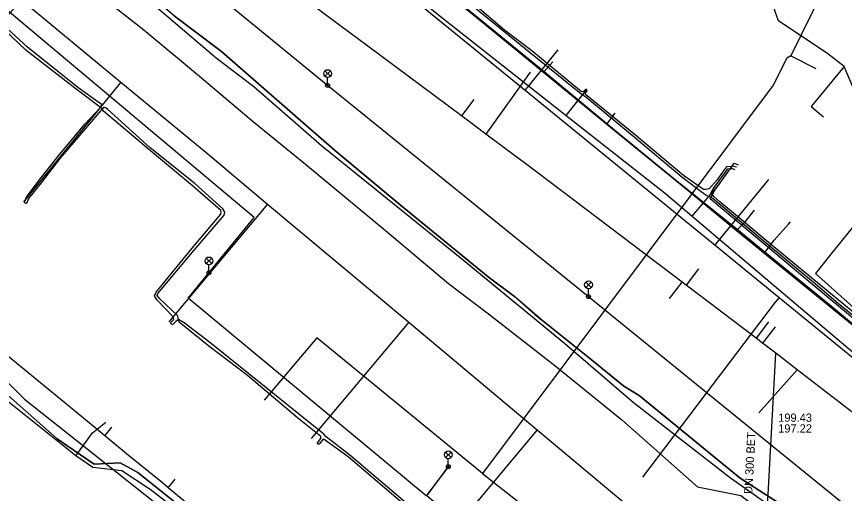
# Model space of a CAD drawing. Extents: x -598932 to -598196, y -1162210 to -1161504.
# Drawn here: x -598553.2 to -598473, y -1161902.1 to -1161855.8 of the extents above; entities that cross this region are included whole.
import ezdxf

# ---------------------------------------------------------------- set-up
doc = ezdxf.new("R2010")
doc.units = 0
for name, color, linetype in [('Vrstva 1', 7, 'Continuous'), ('Vrstva 12', 7, 'Continuous'), ('Vrstva 13', 7, 'Continuous'), ('Vrstva 14', 7, 'Continuous'), ('Vrstva 16', 7, 'Continuous'), ('Vrstva 33', 7, 'Continuous'), ('Vrstva 37', 7, 'Continuous'), ('Vrstva 42', 7, 'Continuous'), ('Vrstva 53', 7, 'Continuous'), ('Vrstva 55', 7, 'Continuous'), ('Vrstva 58', 7, 'Continuous'), ('Vrstva 9', 7, 'Continuous')]:
    doc.layers.add(name, color=color, linetype=linetype)

msp = doc.modelspace()

# ---------------------------------------------------------------- linework, layer by layer
at = {"layer": 'Vrstva 1'}
for p, q in [((-598503.44, -1161861.23), (-598507.733, -1161867.234)), ((-598481.27, -1161894.25), (-598477.545, -1161890.076))]:
    msp.add_line(p, q, dxfattribs=at)
at = {"layer": 'Vrstva 12'}
for p, q in [((-598502.08, -1161861.17), (-598501.22, -1161860.24)), ((-598545.86, -1161896.2), (-598544.55, -1161895.17)), ((-598547.47, -1161898.43), (-598545.86, -1161896.2)), ((-598538.51, -1161901.53), (-598538.57, -1161901.48))]:
    msp.add_line(p, q, dxfattribs=at)
for points in [[(-598614.66, -1161837.53), (-598611.92, -1161843.76), (-598592.64, -1161859.53), (-598589.54, -1161862.06), (-598564.16, -1161882.82), (-598561.07, -1161885.35), (-598555.73, -1161889.71), (-598552.43, -1161892.94), (-598535.8, -1161906.11), (-598532.7, -1161908.64), (-598530.18, -1161910.6)], [(-598515.13, -1161850.5), (-598508.89, -1161855.62), (-598502.08, -1161861.17)], [(-598502.08, -1161861.17), (-598494.86, -1161867.14), (-598489.18, -1161871.8), (-598483.57, -1161876.3), (-598480.65, -1161878.7)], [(-598480.65, -1161878.7), (-598479.77, -1161877.53), (-598478.39, -1161875.98), (-598478.18, -1161875.75)], [(-598480.65, -1161878.7), (-598474.42, -1161883.76), (-598470.49, -1161887.01)], [(-598547.47, -1161898.43), (-598553.93, -1161893.26), (-598560.6, -1161887.07), (-598562.48, -1161886.72), (-598565.94, -1161884.42)], [(-598537.72, -1161903.67), (-598540.27, -1161901.69), (-598543, -1161899.88), (-598545.8, -1161899.55), (-598547.47, -1161898.43)]]:
    msp.add_lwpolyline(points, dxfattribs=at)
at = {"layer": 'Vrstva 13'}
for p, q in [((-598479.34, -1161856.26), (-598481.03, -1161851.54)), ((-598474.59, -1161859.46), (-598479.34, -1161856.26)), ((-598473, -1161860.7), (-598474.59, -1161859.46)), ((-598468.75, -1161870.69), (-598473, -1161860.7)), ((-598544.66, -1161896.48), (-598545.23, -1161896)), ((-598544.66, -1161896.48), (-598543.97, -1161895.64)), ((-598544.27, -1161896.81), (-598544.66, -1161896.48)), ((-598542.54, -1161898.24), (-598544.27, -1161896.81)), ((-598539.21, -1161900.92), (-598542.54, -1161898.24)), ((-598538.57, -1161901.48), (-598539.21, -1161900.92)), ((-598538.51, -1161901.53), (-598537.83, -1161900.7))]:
    msp.add_line(p, q, dxfattribs=at)
for points in [[(-598473, -1161860.7), (-598476.18, -1161864.56), (-598474.98, -1161865.58)], [(-598468.75, -1161870.69), (-598468.37, -1161871.59), (-598474.27, -1161878.88), (-598475.76, -1161880.74), (-598462.19, -1161892.9), (-598455.5, -1161897.81)], [(-598545.23, -1161896), (-598548.52, -1161893.28), (-598563.98, -1161880.65)], [(-598522.28, -1161914.9), (-598529.52, -1161908.95), (-598538.51, -1161901.53)]]:
    msp.add_lwpolyline(points, dxfattribs=at)
at = {"layer": 'Vrstva 14'}
for points in [[(-598589.515, -1161793.152), (-598565.413, -1161812.812), (-598551.541, -1161824.13), (-598545.495, -1161829.063), (-598526.422, -1161844.625), (-598503.906, -1161862.996), (-598485.507, -1161878.008), (-598479.302, -1161883.071), (-598460.805, -1161898.163), (-598459.029, -1161899.612), (-598444.013, -1161911.864), (-598408.629, -1161940.734), (-598391.372, -1161954.815), (-598364.721, -1161976.56), (-598364.173, -1161977.007)], [(-598503.906, -1161862.996), (-598503.673, -1161862.71), (-598500.715, -1161859.086)], [(-598485.507, -1161878.008), (-598485.298, -1161877.752), (-598480.303, -1161871.63)], [(-598479.302, -1161883.071), (-598479.49, -1161883.301), (-598479.681, -1161883.536), (-598492.54, -1161900.5)]]:
    msp.add_lwpolyline(points, dxfattribs=at)
at = {"layer": 'Vrstva 16'}
for p, q in [((-598543.1, -1161862.22), (-598552.54, -1161873.8)), ((-598499.93, -1161865.43), (-598497.94, -1161862.91)), ((-598487.72, -1161875.2), (-598485.01, -1161871.99)), ((-598528.87, -1161874.02), (-598538.44, -1161885.45)), ((-598515.2, -1161885.47), (-598524.66, -1161896.76)), ((-598502.74, -1161895.91), (-598512.06, -1161907.05))]:
    msp.add_line(p, q, dxfattribs=at)
for points in [[(-598589.52, -1161793.04), (-598573.5, -1161806.15), (-598565.11, -1161813.02), (-598552.27, -1161823.54), (-598542.55, -1161831.36), (-598525.09, -1161845.4), (-598512.16, -1161855.8), (-598499.93, -1161865.43), (-598490.31, -1161873), (-598487.72, -1161875.2), (-598464.02, -1161895.26), (-598461.07, -1161897.66), (-598460.06, -1161898.48)], [(-598592.46, -1161832.67), (-598590.88, -1161833.9), (-598577.93, -1161844.56), (-598562.69, -1161857.12), (-598558.59, -1161860.56), (-598552.71, -1161854.24), (-598543.1, -1161862.22), (-598534.68, -1161869.16), (-598528.87, -1161874.02), (-598515.2, -1161885.47), (-598502.74, -1161895.91), (-598494.45, -1161902.85), (-598487.04, -1161908.55)]]:
    msp.add_lwpolyline(points, dxfattribs=at)
at = {"layer": 'Vrstva 33'}
for p, q in [((-598523.325, -1161861.105), (-598522.795, -1161861.635)), ((-598523.325, -1161861.635), (-598522.795, -1161861.105)), ((-598523.06, -1161862.52), (-598523.06, -1161861.745)), ((-598534.825, -1161879.265), (-598534.295, -1161879.795)), ((-598534.825, -1161879.795), (-598534.295, -1161879.265)), ((-598534.56, -1161880.68), (-598534.56, -1161879.905)), ((-598498.035, -1161881.585), (-598497.505, -1161882.115)), ((-598498.035, -1161882.115), (-598497.505, -1161881.585)), ((-598497.77, -1161883), (-598497.77, -1161882.225)), ((-598511.625, -1161898.065), (-598511.095, -1161898.595)), ((-598511.625, -1161898.595), (-598511.095, -1161898.065)), ((-598511.36, -1161899.48), (-598511.36, -1161898.705))]:
    msp.add_line(p, q, dxfattribs=at)
for centre, radius in [((-598523.06, -1161861.37), 0.375), ((-598523.06, -1161862.52), 0.19), ((-598523.06, -1161862.52), 0.05), ((-598534.56, -1161879.53), 0.375), ((-598534.56, -1161880.68), 0.19), ((-598534.56, -1161880.68), 0.05), ((-598497.77, -1161881.85), 0.375), ((-598497.77, -1161883), 0.19), ((-598497.77, -1161883), 0.05), ((-598511.36, -1161898.33), 0.375), ((-598511.36, -1161899.48), 0.19), ((-598511.36, -1161899.48), 0.05)]:
    msp.add_circle(centre, radius, dxfattribs=at)
at = {"layer": 'Vrstva 37'}
msp.add_line((-598478.162, -1161859.647), (-598475.732, -1161860.889), dxfattribs=at)
for points in [[(-598474.045, -1161850.906), (-598473.917, -1161851.012), (-598478.162, -1161859.647)], [(-598478.162, -1161859.647), (-598478.559, -1161859.879), (-598479.87, -1161862.507), (-598508.056, -1161900.133)], [(-598508.056, -1161900.133), (-598524.116, -1161886.989), (-598529.199, -1161893.031)], [(-598508.056, -1161900.133), (-598492.103, -1161912.672), (-598497.677, -1161919.914), (-598469.69, -1161942.486)]]:
    msp.add_lwpolyline(points, dxfattribs=at)
at = {"layer": 'Vrstva 42'}
for points in [[(-598469.718, -1161886.804), (-598473.581, -1161883.647), (-598476.006, -1161881.598), (-598480.307, -1161878.028), (-598483.336, -1161875.479), (-598485.107, -1161873.993), (-598485.725, -1161873.469), (-598485.912, -1161873.387), (-598486.396, -1161873.173), (-598486.84, -1161872.83), (-598488.71, -1161871.42), (-598493.53, -1161867.38), (-598498.036, -1161863.669), (-598498.509, -1161863.332), (-598503.383, -1161859.381), (-598508.91, -1161854.9)], [(-598483.426, -1161870.457), (-598483.833, -1161870.352), (-598483.86, -1161870.356), (-598483.95, -1161870.37), (-598484.391, -1161870.406), (-598484.769, -1161870.929), (-598485.334, -1161871.721), (-598486.07, -1161872.53), (-598486.38, -1161872.62), (-598486.64, -1161872.62), (-598488.58, -1161871.24), (-598493.38, -1161867.21), (-598498.05, -1161863.397), (-598498.073, -1161863.244), (-598497.906, -1161863.058), (-598497.919, -1161862.932), (-598498.059, -1161862.919), (-598498.254, -1161863.114), (-598498.438, -1161863.129), (-598503.27, -1161859.161), (-598505.929, -1161857.17), (-598508.78, -1161854.7)], [(-598537.93, -1161855.79), (-598533.33, -1161859.23), (-598529.5, -1161862.6), (-598522.43, -1161868.76), (-598516.04, -1161874.11), (-598507.5, -1161881.07), (-598504.93, -1161882.99), (-598502.96, -1161884.74), (-598502.366, -1161885.217), (-598497.689, -1161888.976), (-598494.35, -1161891.66), (-598492.87, -1161892.59), (-598483.08, -1161900.58), (-598479.35, -1161903), (-598478.16, -1161903.85), (-598477.85, -1161905.36), (-598479.52, -1161907.76), (-598480.44, -1161908.82), (-598481.38, -1161909.93), (-598482.29, -1161911.96), (-598483.61, -1161914.46)], [(-598544.904, -1161864.809), (-598544.91, -1161864.8), (-598545.06, -1161864.67), (-598547.44, -1161862.87), (-598552.3, -1161859.11), (-598555.11, -1161856.44)], [(-598511.82, -1161906.42), (-598521.08, -1161898.53), (-598523.39, -1161896.85), (-598523.48, -1161896.822), (-598523.894, -1161897.306), (-598524.006, -1161897.294), (-598524.048, -1161897.165), (-598523.73, -1161896.76), (-598523.72, -1161896.54), (-598525.99, -1161894.76), (-598530.82, -1161890.64), (-598534.58, -1161887.81), (-598537.436, -1161885.485), (-598537.51, -1161885.22), (-598537.6, -1161884.82), (-598539.32, -1161883.21), (-598539.59, -1161882.9), (-598539.51, -1161882.69), (-598535.98, -1161878.48), (-598533.09, -1161875.1), (-598533.03, -1161874.81), (-598533.21, -1161874.48), (-598535.94, -1161872.04), (-598540.26, -1161868.56), (-598544.39, -1161864.83), (-598544.51, -1161864.73), (-598544.76, -1161864.63), (-598544.902, -1161864.807), (-598544.904, -1161864.809), (-598545.042, -1161864.949), (-598546.35, -1161866.5), (-598549, -1161869.59), (-598550.82, -1161871.95), (-598552.04, -1161873.49), (-598552.245, -1161873.958), (-598552.388, -1161873.975), (-598552.428, -1161873.836), (-598552.24, -1161873.34), (-598551.01, -1161871.7), (-598549.13, -1161869.36), (-598546.6, -1161866.29), (-598545.06, -1161864.67), (-598544.95, -1161864.38), (-598545.1, -1161864.27), (-598547.28, -1161862.72), (-598552.15, -1161858.81), (-598554.96, -1161856.25)], [(-598511.65, -1161906.22), (-598520.92, -1161898.36), (-598523.2, -1161896.6), (-598523.43, -1161896.33), (-598525.73, -1161894.49), (-598530.7, -1161890.47), (-598534.49, -1161887.45), (-598536.963, -1161885.545), (-598537.51, -1161885.22), (-598537.78, -1161885.4), (-598538.047, -1161885.683), (-598538.211, -1161885.666), (-598538.245, -1161885.519), (-598537.98, -1161885.2), (-598538.05, -1161884.92), (-598539.59, -1161883.35), (-598539.85, -1161882.92), (-598539.68, -1161882.56), (-598536.18, -1161878.3), (-598533.41, -1161874.99), (-598533.37, -1161874.74), (-598533.43, -1161874.61), (-598536.15, -1161872.25), (-598540.41, -1161868.71), (-598544.78, -1161865.01), (-598544.904, -1161864.809)], [(-598463.712, -1161892.08), (-598476.041, -1161881.863), (-598485.979, -1161873.51), (-598485.912, -1161873.387), (-598485.766, -1161873.118), (-598485.524, -1161872.673), (-598484.018, -1161870.576), (-598483.86, -1161870.356), (-598483.653, -1161870.068), (-598483.261, -1161870.216)], [(-598469.58, -1161886.6), (-598475.21, -1161881.96), (-598480.154, -1161877.882), (-598483.125, -1161875.399), (-598485.027, -1161873.804), (-598485.628, -1161873.274), (-598485.766, -1161873.118), (-598485.908, -1161872.958), (-598485.686, -1161872.551), (-598484.602, -1161871.047), (-598484.278, -1161870.601), (-598484.018, -1161870.576), (-598483.85, -1161870.56), (-598483.595, -1161870.667)], [(-598562.907, -1161886.163), (-598560.734, -1161887.05), (-598558.231, -1161888.9), (-598549.262, -1161896.79), (-598548.326, -1161897.417), (-598545.688, -1161899.25), (-598543.156, -1161899.097), (-598541.466, -1161900.059), (-598534.52, -1161905.596)]]:
    msp.add_lwpolyline(points, dxfattribs=at)
at = {"layer": 'Vrstva 53'}
for points in [[(-598548.92, -1161847.63), (-598548.44, -1161848.1), (-598544.77, -1161850.91), (-598540.38, -1161854.29), (-598533.86, -1161859.85), (-598530.21, -1161862.62), (-598523.64, -1161868.33), (-598509.88, -1161879.45), (-598500.11, -1161887.5)], [(-598500.11, -1161887.5), (-598493.43, -1161893.22), (-598484.02, -1161900.57), (-598478.2, -1161904.68), (-598478.06, -1161905.14), (-598479.74, -1161907.98), (-598483.29, -1161912.8), (-598487.83, -1161917.67)]]:
    msp.add_lwpolyline(points, dxfattribs=at)
at = {"layer": 'Vrstva 55'}
for points in [[(-598445.98, -1161975.82), (-598420.69, -1161945.55), (-598428.96, -1161939.09), (-598453.01, -1161919.36), (-598497.77, -1161883), (-598523.06, -1161862.52), (-598551.11, -1161839.54), (-598586.36, -1161810.66), (-598588.39, -1161808.928), (-598593.724, -1161815.599)], [(-598499.78, -1161913.86), (-598513.43, -1161902.32), (-598511.45, -1161899.6), (-598513.52, -1161902.32), (-598536.57, -1161883.13), (-598530.17, -1161875.32), (-598558.96, -1161851.14), (-598564.23, -1161856.6), (-598565.08, -1161856.22), (-598564.32, -1161856.69), (-598566.21, -1161858.86), (-598592.74, -1161836.94), (-598590.93, -1161834.32)]]:
    msp.add_lwpolyline(points, dxfattribs=at)
at = {"layer": 'Vrstva 58'}
msp.add_line((-598495.99, -1161866.27), (-598495.19, -1161865.22), dxfattribs=at)
for points in [[(-598556.07, -1161844.87), (-598550.13, -1161849.77), (-598546.21, -1161852.92), (-598540.88, -1161857.14), (-598535.48, -1161861.63), (-598530.23, -1161866.04), (-598525.2, -1161870.15), (-598517.44, -1161876.59), (-598511.35, -1161881.71), (-598507.47, -1161884.66), (-598501.04, -1161889.68), (-598494.55, -1161894.93), (-598487.2, -1161901.44), (-598483.01, -1161902.28), (-598475.05, -1161908.26), (-598470.42, -1161912.13)], [(-598479.35, -1161903), (-598483.08, -1161900.58), (-598492.87, -1161892.59), (-598494.35, -1161891.66), (-598497.689, -1161888.976), (-598502.366, -1161885.217), (-598504.93, -1161882.99), (-598507.5, -1161881.07), (-598516.04, -1161874.11), (-598522.43, -1161868.76), (-598529.5, -1161862.6), (-598533.33, -1161859.23), (-598537.93, -1161855.79), (-598544.08, -1161850.56), (-598547.91, -1161847.44), (-598550.17, -1161845.76)], [(-598603.585, -1161846.543), (-598604.434, -1161847.56), (-598602.839, -1161849.016), (-598602.221, -1161849.717), (-598597.187, -1161854.097), (-598591.703, -1161858.144), (-598588.562, -1161861.055), (-598584, -1161864.794), (-598583.326, -1161866.362), (-598583.12, -1161868.355), (-598581.997, -1161871.161), (-598572.083, -1161878.904), (-598562.907, -1161886.163), (-598560.734, -1161887.05), (-598558.231, -1161888.9), (-598549.262, -1161896.79), (-598545.688, -1161899.25), (-598543.156, -1161899.097), (-598541.466, -1161900.059), (-598534.52, -1161905.596), (-598528.543, -1161910.378), (-598519.292, -1161918.334), (-598514.716, -1161921.934)], [(-598514.7, -1161851.03), (-598513.78, -1161851.82), (-598510.99, -1161853.98), (-598504.8, -1161859.05), (-598495.99, -1161866.27)], [(-598537.93, -1161855.79), (-598533.33, -1161859.23), (-598529.5, -1161862.6), (-598522.43, -1161868.76), (-598516.04, -1161874.11), (-598507.5, -1161881.07), (-598504.93, -1161882.99), (-598502.96, -1161884.74), (-598502.366, -1161885.217), (-598497.689, -1161888.976), (-598494.35, -1161891.66), (-598492.87, -1161892.59), (-598483.08, -1161900.58), (-598479.35, -1161903), (-598478.16, -1161903.85), (-598477.85, -1161905.36), (-598479.52, -1161907.76), (-598480.44, -1161908.82), (-598481.38, -1161909.93), (-598482.29, -1161911.96), (-598483.61, -1161914.46)], [(-598495.99, -1161866.27), (-598488.66, -1161872.24), (-598486.05, -1161874.41), (-598483.42, -1161876.6)], [(-598483.42, -1161876.6), (-598482.55, -1161875.7), (-598481.683, -1161874.613)], [(-598483.42, -1161876.6), (-598465.64, -1161891.05), (-598463.79, -1161892.51), (-598463.73, -1161892.75), (-598471.66, -1161902.84), (-598472.18, -1161903.75), (-598472.54, -1161904.36), (-598474.35, -1161906.56), (-598474.76, -1161907.47), (-598474.96, -1161908.4), (-598474.81, -1161909.14)], [(-598534.52, -1161905.596), (-598541.466, -1161900.059), (-598543.156, -1161899.097), (-598545.688, -1161899.25), (-598548.326, -1161897.417), (-598549.262, -1161896.79), (-598558.231, -1161888.9), (-598560.734, -1161887.05), (-598562.907, -1161886.163)]]:
    msp.add_lwpolyline(points, dxfattribs=at)
at = {"layer": 'Vrstva 9'}
for p, q in [((-598508.888, -1161863.88), (-598510.083, -1161865.484)), ((-598487.096, -1161880.302), (-598488.303, -1161881.897)), ((-598489.918, -1161883.182), (-598488.709, -1161881.589)), ((-598480.327, -1161885.426), (-598481.534, -1161887.021)), ((-598479.689, -1161885.909), (-598480.896, -1161887.504)), ((-598480.59, -1161906.42), (-598479.62, -1161888.47))]:
    msp.add_line(p, q, dxfattribs=at)
for points in [[(-598503.98, -1161870.03), (-598504.702, -1161869.492), (-598507.733, -1161867.234), (-598510.083, -1161865.484), (-598519.153, -1161858.727), (-598528.76, -1161851.57)], [(-598479.62, -1161888.47), (-598480.896, -1161887.504), (-598481.534, -1161887.021), (-598488.303, -1161881.897), (-598488.709, -1161881.589), (-598503.98, -1161870.03)], [(-598452.38, -1161909.55), (-598458.098, -1161905.125), (-598462.179, -1161901.967), (-598462.218, -1161901.937), (-598472.08, -1161894.305), (-598477.545, -1161890.076), (-598479.62, -1161888.47)]]:
    msp.add_lwpolyline(points, dxfattribs=at)

# ---------------------------------------------------------------- texts
at = {"layer": 'Vrstva 12'}
for s, p in [('199.43', (-598479.386, -1161895.125)), ('197.22', (-598479.386, -1161896.175))]:
    msp.add_text(s, height=0.8, dxfattribs=at).set_placement(p)
msp.add_text('DN 300 BET', height=0.8, rotation=87, dxfattribs=at).set_placement((-598481.894, -1161902.146))

doc.saveas('drawing.dxf')
